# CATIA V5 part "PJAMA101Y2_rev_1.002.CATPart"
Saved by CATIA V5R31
Part number: JAMA101Y2
Revision: 1
Nomenclature: BRACE_F
Source: Unknown
Property "部品番号(A社)": "JAMA101Y2"
Property "部品名称(A社)": "BRACE_F"
Property "Version(A社)": "1"
Property "材質(A社)": "SPHN2"
Property "板厚": "2.3"
Bounding box of the stored display mesh (mm): x 4110.044 to 4301.836, y 295 to 583.063, z 620.856 to 889.708
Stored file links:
  \\solize.local\damia\dept\DDE_Design\10_order\2305701_JAMA_変換検証STEP3_お手本モデル作成\work\02_マツダ_板金\10_CATIA_V5\231211\PJAMA101Y2_rev_1.002.CATPart
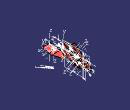
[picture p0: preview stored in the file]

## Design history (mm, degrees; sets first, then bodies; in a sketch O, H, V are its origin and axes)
TTRSSet1
f4a2d38f3ddc11d3a929006094b99c4b_11 "CATTPSSet"
Set1
  DatumSurface1 "OPEN_SHELL #618"
Set2 "DATUM"
  Point1 to Point10: stored without definition
  Point11: type OnCurve, Support edge of DatumSurface1, Ratio 0.5
  Point12: type OnCurve, Support edge of DatumSurface1, Ratio 0.5
  Point13: stored without definition
  AxisSystem1: origin (4236.4075, 538, 829), X (-0.4695, 0, -0.8829), Y (0, 1, 0), Z (0.8829, 0, -0.4695)
  AxisSystem2: origin (4214.426, 540, 787.659), X (0.4695, 0, 0.8829), Y (0, 1, 0), Z (-0.8829, 0, 0.4695)
  AxisSystem3: origin (4205.0366, 540, 770), X (0.4695, 0, 0.8829), Y (0, 1, 0), Z (-0.8829, 0, 0.4695)
  AxisSystem4: origin (4176.6608, 538.0877, 716.641), X (-0.3018, 0.766, -0.5675), Y (-0.3596, -0.6428, -0.6764), Z (0.8829, 0, -0.4695)
  AxisSystem5: origin (4150, 468, 678), X (-0.262, 0.8298, -0.4927), Y (0.3896, 0.558, 0.7327), Z (0.8829, 0, -0.4695)
  AxisSystem6: origin (4161, 307, 701.7), X (1, 0, 0), Y (0, 1, 0), Z (0, 0, 1)
  AxisSystem7: origin (4170, 346.9, 701.7), X (1, 0, 0), Y (0, -1, 0), Z (0, 0, -1)
  AxisSystem8: origin (4276, 518.7, 860), X (1, 0, 0), Y (0, 0, 1), Z (0, -1, 0)
  AxisSystem9: origin (4194.4024, 540, 750), X (0, -1, 0), Y (-0.4695, 0, -0.8829), Z (0.8829, 0, -0.4695)
  Sketch1 on ZX plane of AxisSystem8, origin (4276, 518.7, 860), H (0, -1, 0), V (1, 0, 0)
    point P1 (-11.554, 7.8076)
    line L1 (-11.554, 7.8076) -> (-26.554, 7.8076)
    point P2 (-26.554, 7.8076)
    line L2 (-26.554, 7.8076) -> (-21.554, 9.1474)
    line L3 (-26.554, 7.8076) -> (-21.554, 6.4679)
    construction line L4 (-21.554, 9.1474) -> (-21.554, 6.4679)
    angle L2 L3 = 30
    distance P2 L4 = 5
    distance P1 L4 = 10
    horizontal: L1 H
    symmetry: L2 L3 L1
    vertical: L4 V
Set3 "CURVE"
  DatumCurve1 to DatumCurve4
  DatumSurface2 to DatumSurface4
  DatumCurve5 to DatumCurve7
  Circle1: stored without definition
  Circle2: stored without definition
Body1 (main body)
